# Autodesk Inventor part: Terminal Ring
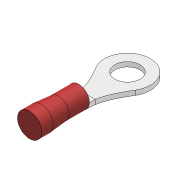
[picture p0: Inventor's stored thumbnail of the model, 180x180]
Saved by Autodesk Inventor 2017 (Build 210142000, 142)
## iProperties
Created: 2016-11
Part Number: Terminal Ring
Material: Generic
Document SubType Name: Modeling
Designer: DanielSeverino
Density: 1 g/cm^3
Appearance: Default
Company: Autodesk Inc.
GlobalPropertyList: <PropertyList/>
Title: C:\Users\DanielSeverino\Desktop\Terminal Ring.stp
Author: DanielSeverino
Sending System: Autodesk Inventor 2017
Preprocessor: ST-DEVELOPER v16.5
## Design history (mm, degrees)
feature "Solid1"
body "Solid2"
